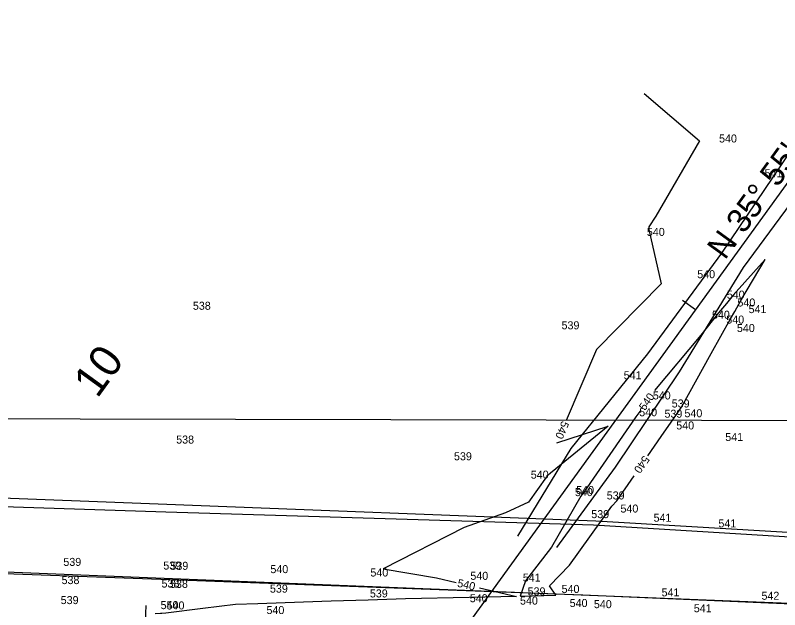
# Model space of a CAD drawing. Extents: x 1787461 to 1970323, y 938412 to 1118748.
# Drawn here: x 1968745.6 to 1968936.6, y 1117917.1 to 1118065.5 of the extents above; entities that cross this region are included whole.
import ezdxf

# ---------------------------------------------------------------- set-up
doc = ezdxf.new("R2010")
doc.units = 0
for name, color, linetype in [('Default', 7, 'Continuous'), ('HHA ADDITIONAL XSs', 7, 'Continuous'), ('RD_EX_Fence_Other', 7, 'Continuous'), ('RD_EX_H2O', 7, 'Continuous'), ('RD_EX_Road', 7, 'Continuous'), ('RD_EX_VEG', 7, 'Continuous'), ('RD_HC_CL', 7, 'Continuous'), ('RD_HC_Data', 7, 'Continuous'), ('RD_HC_Data_Tic', 7, 'Continuous'), ('RD_HC_TX_Sta50', 7, 'Continuous'), ('RD_PD_Final_TrvlWay', 7, 'Continuous')]:
    doc.layers.add(name, color=color, linetype=linetype)

msp = doc.modelspace()

# ---------------------------------------------------------------- linework, layer by layer
at = {"layer": 'Default'}
for points in [[(1968902.75, 1118045.96), (1968916.58, 1118034.22), (1968905.72, 1118015.4), (1968903.9, 1118012.67), (1968903.89, 1118012.06), (1968907.05, 1117998.5), (1968890.88, 1117982.08), (1968883.3, 1117964.36)], [(1968902.75, 1118045.96), (1968916.58, 1118034.22), (1968905.72, 1118015.4), (1968903.9, 1118012.67), (1968903.89, 1118012.06), (1968907.05, 1117998.5), (1968890.88, 1117982.08), (1968883.3, 1117964.36)], [(1968902.75, 1118045.96), (1968916.58, 1118034.22), (1968905.72, 1118015.4), (1968903.9, 1118012.67), (1968903.89, 1118012.06), (1968907.05, 1117998.5), (1968890.88, 1117982.08), (1968883.3, 1117964.36)], [(1968902.75, 1118045.96), (1968916.58, 1118034.22), (1968905.72, 1118015.4), (1968903.9, 1118012.67), (1968903.89, 1118012.06), (1968907.05, 1117998.5), (1968890.88, 1117982.08), (1968883.3, 1117964.36)], [(1968902.75, 1118045.96), (1968916.58, 1118034.22), (1968905.72, 1118015.4), (1968903.9, 1118012.67), (1968903.89, 1118012.06), (1968907.05, 1117998.5), (1968890.88, 1117982.08), (1968883.3, 1117964.36)], [(1968902.75, 1118045.96), (1968916.58, 1118034.22), (1968905.72, 1118015.4), (1968903.9, 1118012.67), (1968903.89, 1118012.06), (1968907.05, 1117998.5), (1968890.88, 1117982.08), (1968883.3, 1117964.36)], [(1968902.75, 1118045.96), (1968916.58, 1118034.22), (1968905.72, 1118015.4), (1968903.9, 1118012.67), (1968903.89, 1118012.06), (1968907.05, 1117998.5), (1968890.88, 1117982.08), (1968883.3, 1117964.36)], [(1968903.68, 1117955.5), (1968907.04, 1117960.35), (1968910.1, 1117964.8), (1968911.72, 1117967.14), (1968912.11, 1117967.71), (1968919.53, 1117981.04), (1968924.36, 1117989.7), (1968925.38, 1117991.54), (1968926.92, 1117994.32), (1968932.96, 1118004.55), (1968924.98, 1117995.63), (1968923.35, 1117993.57), (1968921.38, 1117991.2), (1968916.96, 1117985.68), (1968905.32, 1117971.84)], [(1968903.68, 1117955.5), (1968907.04, 1117960.35), (1968910.1, 1117964.8), (1968911.72, 1117967.14), (1968912.11, 1117967.71), (1968919.53, 1117981.04), (1968924.36, 1117989.7), (1968925.38, 1117991.54), (1968926.92, 1117994.32), (1968932.96, 1118004.55), (1968924.98, 1117995.63), (1968923.35, 1117993.57), (1968921.38, 1117991.2), (1968916.96, 1117985.68), (1968905.32, 1117971.84)], [(1968903.68, 1117955.5), (1968907.04, 1117960.35), (1968910.1, 1117964.8), (1968911.72, 1117967.14), (1968912.11, 1117967.71), (1968919.53, 1117981.04), (1968924.36, 1117989.7), (1968925.38, 1117991.54), (1968926.92, 1117994.32), (1968932.96, 1118004.55), (1968924.98, 1117995.63), (1968923.35, 1117993.57), (1968921.38, 1117991.2), (1968916.96, 1117985.68), (1968905.32, 1117971.84)], [(1968903.68, 1117955.5), (1968907.04, 1117960.35), (1968910.1, 1117964.8), (1968911.72, 1117967.14), (1968912.11, 1117967.71), (1968919.53, 1117981.04), (1968924.36, 1117989.7), (1968925.38, 1117991.54), (1968926.92, 1117994.32), (1968932.96, 1118004.55), (1968924.98, 1117995.63), (1968923.35, 1117993.57), (1968921.38, 1117991.2), (1968916.96, 1117985.68), (1968905.32, 1117971.84)], [(1968903.68, 1117955.5), (1968907.04, 1117960.35), (1968910.1, 1117964.8), (1968911.72, 1117967.14), (1968912.11, 1117967.71), (1968919.53, 1117981.04), (1968924.36, 1117989.7), (1968925.38, 1117991.54), (1968926.92, 1117994.32), (1968932.96, 1118004.55), (1968924.98, 1117995.63), (1968923.35, 1117993.57), (1968921.38, 1117991.2), (1968916.96, 1117985.68), (1968905.32, 1117971.84)], [(1968903.68, 1117955.5), (1968907.04, 1117960.35), (1968910.1, 1117964.8), (1968911.72, 1117967.14), (1968912.11, 1117967.71), (1968919.53, 1117981.04), (1968924.36, 1117989.7), (1968925.38, 1117991.54), (1968926.92, 1117994.32), (1968932.96, 1118004.55), (1968924.98, 1117995.63), (1968923.35, 1117993.57), (1968921.38, 1117991.2), (1968916.96, 1117985.68), (1968905.32, 1117971.84)], [(1968903.68, 1117955.5), (1968907.04, 1117960.35), (1968910.1, 1117964.8), (1968911.72, 1117967.14), (1968912.11, 1117967.71), (1968919.53, 1117981.04), (1968924.36, 1117989.7), (1968925.38, 1117991.54), (1968926.92, 1117994.32), (1968932.96, 1118004.55), (1968924.98, 1117995.63), (1968923.35, 1117993.57), (1968921.38, 1117991.2), (1968916.96, 1117985.68), (1968905.32, 1117971.84)], [(1968901.91, 1117966.9), (1968900.68, 1117965.24)], [(1968901.91, 1117966.9), (1968900.68, 1117965.24)], [(1968901.91, 1117966.9), (1968900.68, 1117965.24)], [(1968901.91, 1117966.9), (1968900.68, 1117965.24)], [(1968901.91, 1117966.9), (1968900.68, 1117965.24)], [(1968901.91, 1117966.9), (1968900.68, 1117965.24)], [(1968901.91, 1117966.9), (1968900.68, 1117965.24)], [(1968900.68, 1117965.24), (1968888.43, 1117947.53), (1968887.16, 1117945.8), (1968886.96, 1117945.45), (1968879.58, 1117932.74), (1968873.07, 1117924.32), (1968871.8, 1117920.45), (1968880.7, 1117920.74), (1968879.1, 1117923.08), (1968884.09, 1117928.23), (1968894.72, 1117942.96), (1968895.9, 1117944.26), (1968900.27, 1117950.57)], [(1968900.68, 1117965.24), (1968888.43, 1117947.53), (1968887.16, 1117945.8), (1968886.96, 1117945.45), (1968879.58, 1117932.74), (1968873.07, 1117924.32), (1968871.8, 1117920.45), (1968880.7, 1117920.74), (1968879.1, 1117923.08), (1968884.09, 1117928.23), (1968894.72, 1117942.96), (1968895.9, 1117944.26), (1968900.27, 1117950.57)], [(1968900.68, 1117965.24), (1968888.43, 1117947.53), (1968887.16, 1117945.8), (1968886.96, 1117945.45), (1968879.58, 1117932.74), (1968873.07, 1117924.32), (1968871.8, 1117920.45), (1968880.7, 1117920.74), (1968879.1, 1117923.08), (1968884.09, 1117928.23), (1968894.72, 1117942.96), (1968895.9, 1117944.26), (1968900.27, 1117950.57)], [(1968900.68, 1117965.24), (1968888.43, 1117947.53), (1968887.16, 1117945.8), (1968886.96, 1117945.45), (1968879.58, 1117932.74), (1968873.07, 1117924.32), (1968871.8, 1117920.45), (1968880.7, 1117920.74), (1968879.1, 1117923.08), (1968884.09, 1117928.23), (1968894.72, 1117942.96), (1968895.9, 1117944.26), (1968900.27, 1117950.57)], [(1968900.68, 1117965.24), (1968888.43, 1117947.53), (1968887.16, 1117945.8), (1968886.96, 1117945.45), (1968879.58, 1117932.74), (1968873.07, 1117924.32), (1968871.8, 1117920.45), (1968880.7, 1117920.74), (1968879.1, 1117923.08), (1968884.09, 1117928.23), (1968894.72, 1117942.96), (1968895.9, 1117944.26), (1968900.27, 1117950.57)], [(1968900.68, 1117965.24), (1968888.43, 1117947.53), (1968887.16, 1117945.8), (1968886.96, 1117945.45), (1968879.58, 1117932.74), (1968873.07, 1117924.32), (1968871.8, 1117920.45), (1968880.7, 1117920.74), (1968879.1, 1117923.08), (1968884.09, 1117928.23), (1968894.72, 1117942.96), (1968895.9, 1117944.26), (1968900.27, 1117950.57)], [(1968900.68, 1117965.24), (1968888.43, 1117947.53), (1968887.16, 1117945.8), (1968886.96, 1117945.45), (1968879.58, 1117932.74), (1968873.07, 1117924.32), (1968871.8, 1117920.45), (1968880.7, 1117920.74), (1968879.1, 1117923.08), (1968884.09, 1117928.23), (1968894.72, 1117942.96), (1968895.9, 1117944.26), (1968900.27, 1117950.57)], [(1968880.94, 1117958.84), (1968880.9, 1117958.75), (1968893.8, 1117962.97), (1968878.47, 1117950.47), (1968878.34, 1117950.29), (1968873.82, 1117943.92), (1968868.15, 1117941.32), (1968857.81, 1117937.63), (1968837.55, 1117927.3), (1968850.84, 1117925.08), (1968855.79, 1117923.93)], [(1968880.94, 1117958.84), (1968880.9, 1117958.75), (1968893.8, 1117962.97), (1968878.47, 1117950.47), (1968878.34, 1117950.29), (1968873.82, 1117943.92), (1968868.15, 1117941.32), (1968857.81, 1117937.63), (1968837.55, 1117927.3), (1968850.84, 1117925.08), (1968855.79, 1117923.93)], [(1968880.94, 1117958.84), (1968880.9, 1117958.75), (1968893.8, 1117962.97), (1968878.47, 1117950.47), (1968878.34, 1117950.29), (1968873.82, 1117943.92), (1968868.15, 1117941.32), (1968857.81, 1117937.63), (1968837.55, 1117927.3), (1968850.84, 1117925.08), (1968855.79, 1117923.93)], [(1968880.94, 1117958.84), (1968880.9, 1117958.75), (1968893.8, 1117962.97), (1968878.47, 1117950.47), (1968878.34, 1117950.29), (1968873.82, 1117943.92), (1968868.15, 1117941.32), (1968857.81, 1117937.63), (1968837.55, 1117927.3), (1968850.84, 1117925.08), (1968855.79, 1117923.93)], [(1968880.94, 1117958.84), (1968880.9, 1117958.75), (1968893.8, 1117962.97), (1968878.47, 1117950.47), (1968878.34, 1117950.29), (1968873.82, 1117943.92), (1968868.15, 1117941.32), (1968857.81, 1117937.63), (1968837.55, 1117927.3), (1968850.84, 1117925.08), (1968855.79, 1117923.93)], [(1968880.94, 1117958.84), (1968880.9, 1117958.75), (1968893.8, 1117962.97), (1968878.47, 1117950.47), (1968878.34, 1117950.29), (1968873.82, 1117943.92), (1968868.15, 1117941.32), (1968857.81, 1117937.63), (1968837.55, 1117927.3), (1968850.84, 1117925.08), (1968855.79, 1117923.93)], [(1968880.94, 1117958.84), (1968880.9, 1117958.75), (1968893.8, 1117962.97), (1968878.47, 1117950.47), (1968878.34, 1117950.29), (1968873.82, 1117943.92), (1968868.15, 1117941.32), (1968857.81, 1117937.63), (1968837.55, 1117927.3), (1968850.84, 1117925.08), (1968855.79, 1117923.93)], [(1968861.63, 1117922.57), (1968870.88, 1117920.42), (1968859.05, 1117920.15), (1968843.14, 1117919.79), (1968833.78, 1117919.48), (1968824.56, 1117919.24), (1968808.49, 1117918.66), (1968806.26, 1117918.6), (1968800.67, 1117918.38), (1968792.48, 1117917.44), (1968783.27, 1117916.27), (1968782.21, 1117916.19), (1968781.9, 1117916.17), (1968780.54, 1117916.07)], [(1968861.63, 1117922.57), (1968870.88, 1117920.42), (1968859.05, 1117920.15), (1968843.14, 1117919.79), (1968833.78, 1117919.48), (1968824.56, 1117919.24), (1968808.49, 1117918.66), (1968806.26, 1117918.6), (1968800.67, 1117918.38), (1968792.48, 1117917.44), (1968783.27, 1117916.27), (1968782.21, 1117916.19), (1968781.9, 1117916.17), (1968780.54, 1117916.07)], [(1968861.63, 1117922.57), (1968870.88, 1117920.42), (1968859.05, 1117920.15), (1968843.14, 1117919.79), (1968833.78, 1117919.48), (1968824.56, 1117919.24), (1968808.49, 1117918.66), (1968806.26, 1117918.6), (1968800.67, 1117918.38), (1968792.48, 1117917.44), (1968783.27, 1117916.27), (1968782.21, 1117916.19), (1968781.9, 1117916.17), (1968780.54, 1117916.07)], [(1968861.63, 1117922.57), (1968870.88, 1117920.42), (1968859.05, 1117920.15), (1968843.14, 1117919.79), (1968833.78, 1117919.48), (1968824.56, 1117919.24), (1968808.49, 1117918.66), (1968806.26, 1117918.6), (1968800.67, 1117918.38), (1968792.48, 1117917.44), (1968783.27, 1117916.27), (1968782.21, 1117916.19), (1968781.9, 1117916.17), (1968780.54, 1117916.07)], [(1968861.63, 1117922.57), (1968870.88, 1117920.42), (1968859.05, 1117920.15), (1968843.14, 1117919.79), (1968833.78, 1117919.48), (1968824.56, 1117919.24), (1968808.49, 1117918.66), (1968806.26, 1117918.6), (1968800.67, 1117918.38), (1968792.48, 1117917.44), (1968783.27, 1117916.27), (1968782.21, 1117916.19), (1968781.9, 1117916.17), (1968780.54, 1117916.07)], [(1968861.63, 1117922.57), (1968870.88, 1117920.42), (1968859.05, 1117920.15), (1968843.14, 1117919.79), (1968833.78, 1117919.48), (1968824.56, 1117919.24), (1968808.49, 1117918.66), (1968806.26, 1117918.6), (1968800.67, 1117918.38), (1968792.48, 1117917.44), (1968783.27, 1117916.27), (1968782.21, 1117916.19), (1968781.9, 1117916.17), (1968780.54, 1117916.07)], [(1968861.63, 1117922.57), (1968870.88, 1117920.42), (1968859.05, 1117920.15), (1968843.14, 1117919.79), (1968833.78, 1117919.48), (1968824.56, 1117919.24), (1968808.49, 1117918.66), (1968806.26, 1117918.6), (1968800.67, 1117918.38), (1968792.48, 1117917.44), (1968783.27, 1117916.27), (1968782.21, 1117916.19), (1968781.9, 1117916.17), (1968780.54, 1117916.07)]]:
    msp.add_lwpolyline(points, dxfattribs=at)
at = {"layer": 'HHA ADDITIONAL XSs'}
msp.add_lwpolyline([(1969266.55, 1117963.61), (1967907.56, 1117966.55), (1967403.98, 1117771.66), (1967075.57, 1117641.84)], dxfattribs=at)
at = {"layer": 'RD_EX_Fence_Other'}
msp.add_lwpolyline([(1968536.3, 1117952.23), (1968681.42, 1117947.34), (1968783.46, 1117943.44), (1968890.68, 1117939.26), (1968990.9, 1117933.42), (1969093.99, 1117930.77), (1969190.99, 1117925.01), (1969281.24, 1117923.59)], dxfattribs=at)
at = {"layer": 'RD_EX_H2O'}
for points in [[(1968871.21, 1117935.49), (1968884.56, 1117957.36), (1968903.71, 1117980.96), (1968922.18, 1118006.14), (1968939.33, 1118031.51)], [(1968880.9, 1117932.65), (1968895.62, 1117952.72), (1968911.6, 1117976.52), (1968927.62, 1118002.53), (1968945.88, 1118027.35)]]:
    msp.add_lwpolyline(points, dxfattribs=at)
at = {"layer": 'RD_EX_Road'}
msp.add_lwpolyline([(1968529.31, 1117935.06), (1968680.74, 1117928.37), (1968782, 1117924.72), (1968887.41, 1117920.79), (1968989.99, 1117916.45), (1969090.76, 1117912.42), (1969189.86, 1117908.01), (1969282.04, 1117904.78)], dxfattribs=at)
at = {"layer": 'RD_EX_VEG'}
msp.add_lwpolyline([(1968535.19, 1117951.62), (1968681.64, 1117944.89), (1968783.26, 1117941.54), (1968890.11, 1117938.32), (1968991.04, 1117932.18), (1969094.36, 1117929.93), (1969190.81, 1117923.37), (1969281.69, 1117922.69)], dxfattribs=at)
at = {"layer": 'RD_HC_CL'}
msp.add_line((1968856.94, 1117911.01), (1968968.89, 1118065.53), dxfattribs=at)
at = {"layer": 'RD_HC_Data_Tic'}
for p, q in [((1968915.61, 1117991.99), (1968912.37, 1117994.34)), ((1968778.18, 1117914.14), (1968778.34, 1117918.14))]:
    msp.add_line(p, q, dxfattribs=at)
at = {"layer": 'RD_PD_Final_TrvlWay'}
msp.add_line((1968478.85, 1117937.03), (1969278.22, 1117905.3), dxfattribs=at)

# ---------------------------------------------------------------- texts
at = {"layer": 'Default'}
for s, p in [('540', (1968921.48, 1118033.77)), ('541', (1968932.86, 1118025.08)), ('540', (1968903.44, 1118010.44)), ('540', (1968916.03, 1117999.88)), ('540', (1968923.41, 1117994.78)), ('540', (1968926.07, 1117992.82)), ('538', (1968789.99, 1117992)), ('541', (1968928.85, 1117991.17)), ('540', (1968919.72, 1117989.76)), ('540', (1968923.29, 1117988.55)), ('539', (1968882.12, 1117987.12)), ('540', (1968925.94, 1117986.45)), ('541', (1968897.65, 1117974.64)), ('540', (1968904.93, 1117969.61)), ('539', (1968909.65, 1117967.6)), ('540', (1968901.53, 1117965.41)), ('539', (1968907.84, 1117965.04)), ('540', (1968912.83, 1117965.16)), ('540', (1968910.78, 1117962.12)), ('538', (1968785.82, 1117958.59)), ('541', (1968923.03, 1117959.23)), ('539', (1968855.24, 1117954.42)), ('540', (1968874.43, 1117949.83)), ('540', (1968885.46, 1117945.47)), ('540', (1968885.78, 1117946)), ('539', (1968893.41, 1117944.64)), ('540', (1968896.84, 1117941.36)), ('539', (1968889.55, 1117939.97)), ('541', (1968905.11, 1117939.08)), ('541', (1968921.32, 1117937.66)), ('539', (1968757.62, 1117928.04)), ('539', (1968782.6, 1117927.13)), ('539', (1968784.38, 1117927.07)), ('540', (1968809.36, 1117926.24)), ('540', (1968834.35, 1117925.4)), ('538', (1968757.17, 1117923.5)), ('540', (1968859.33, 1117924.57)), ('541', (1968872.44, 1117924.13)), ('538', (1968782.16, 1117922.64)), ('538', (1968784.28, 1117922.56)), ('539', (1968809.25, 1117921.37)), ('539', (1968834.22, 1117920.17)), ('539', (1968873.64, 1117920.68)), ('540', (1968882.13, 1117921.29)), ('541', (1968907.11, 1117920.44)), ('539', (1968756.96, 1117918.51)), ('540', (1968859.19, 1117918.98)), ('540', (1968871.74, 1117918.38)), ('540', (1968884.15, 1117917.78)), ('542', (1968932.08, 1117919.59)), ('540', (1968781.92, 1117917.25)), ('540', (1968783.42, 1117917.17)), ('540', (1968808.38, 1117916.02)), ('540', (1968890.2, 1117917.49)), ('541', (1968915.17, 1117916.47))]:
    msp.add_text(s, height=2, dxfattribs=at).set_placement(p)
for rotation, p in [(55.3463, (1968902.95, 1117966.66)), (55.3463, (1968902.95, 1117966.66)), (55.3463, (1968902.95, 1117966.66)), (55.3463, (1968902.95, 1117966.66)), (55.3463, (1968902.95, 1117966.66)), (55.3463, (1968902.95, 1117966.66)), (55.3463, (1968902.95, 1117966.66)), (246.8392, (1968882.23, 1117964.39)), (246.8392, (1968882.23, 1117964.39)), (246.8392, (1968882.23, 1117964.39)), (246.8392, (1968882.23, 1117964.39)), (246.8392, (1968882.23, 1117964.39)), (246.8392, (1968882.23, 1117964.39)), (246.8392, (1968882.23, 1117964.39)), (235.3093, (1968902.63, 1117955.75)), (235.3093, (1968902.63, 1117955.75)), (235.3093, (1968902.63, 1117955.75)), (235.3093, (1968902.63, 1117955.75)), (235.3093, (1968902.63, 1117955.75)), (235.3093, (1968902.63, 1117955.75)), (235.3093, (1968902.63, 1117955.75)), (346.8963, (1968855.94, 1117922.87)), (346.8963, (1968855.94, 1117922.87)), (346.8963, (1968855.94, 1117922.87)), (346.8963, (1968855.94, 1117922.87)), (346.8963, (1968855.94, 1117922.87)), (346.8963, (1968855.94, 1117922.87)), (346.8963, (1968855.94, 1117922.87))]:
    msp.add_text('540', height=2, rotation=rotation, dxfattribs=at).set_placement(p)
at = {"layer": 'RD_HC_Data'}
msp.add_text('N 35%%d 55\' 22" E', height=6, rotation=54.0772, dxfattribs=at).set_placement((1968922.95, 1118004.24))
at = {"layer": 'RD_HC_TX_Sta50'}
msp.add_text('10', height=8, rotation=54.0772, dxfattribs=at).set_placement((1968766.09, 1117969.68))

doc.saveas('drawing.dxf')
